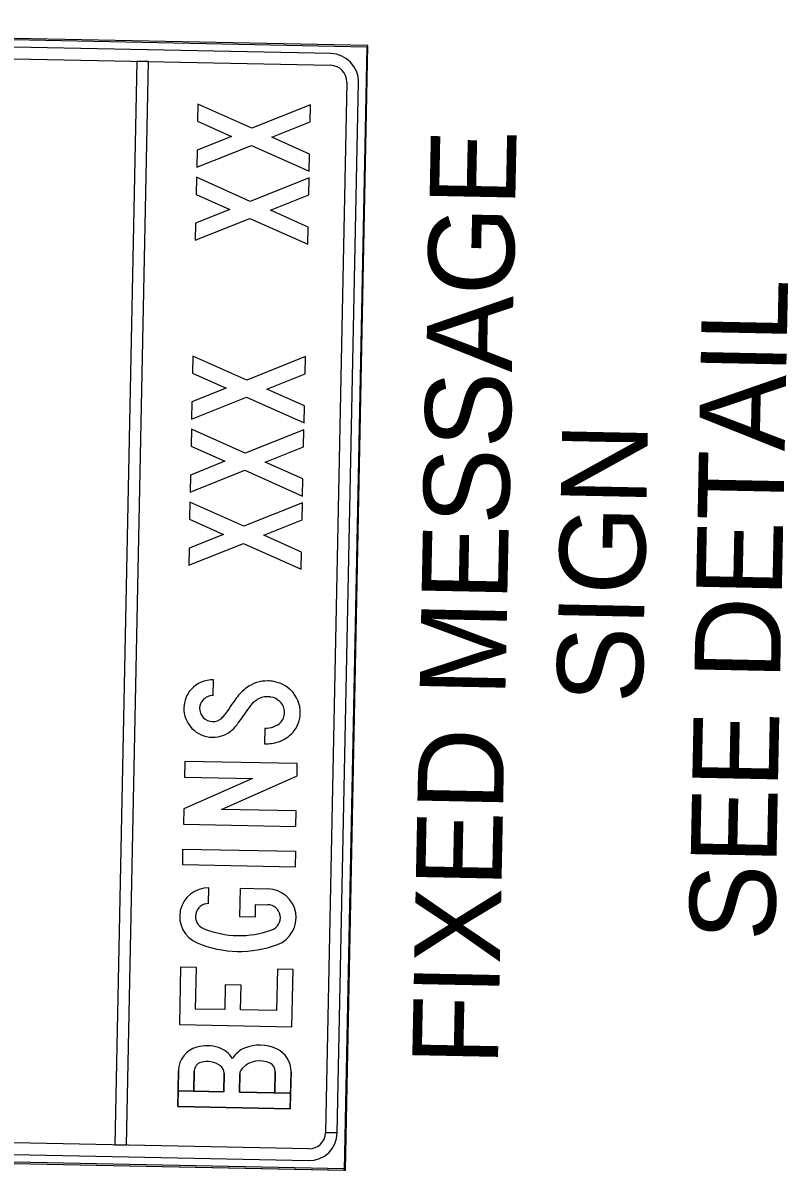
# Model space of a CAD drawing. Extents: x 331323 to 388339, y 121519 to 205315.
# Drawn here: x 366277 to 366812, y 140157 to 140960 of the extents above; entities that cross this region are included whole.
import ezdxf

# ---------------------------------------------------------------- set-up
doc = ezdxf.new("R2010")
doc.units = 0
doc.layers.add('CA-TEXT', color=7, linetype='Continuous')
doc.layers.add('P_MISC_TXT', color=7, linetype='Continuous')

msp = doc.modelspace()

# ---------------------------------------------------------------- linework, layer by layer
at = {"layer": 'CA-TEXT'}
for p, q in [((366518.36, 140944.39), (365730.94, 140960.23)), ((365731.75, 140959.39), (366517.53, 140943.58)), ((366492.41, 140938.75), (365756.65, 140953.56)), ((365756.49, 140945.36), (366492.24, 140930.55)), ((366517.53, 140943.58), (366501.7, 140156.98)), ((366502.52, 140156.97), (366518.36, 140944.39)), ((366503.49, 140918.84), (366488.69, 140183.17)), ((366496.89, 140183), (366511.69, 140918.68)), ((366406.84, 140343.58), (366407.06, 140354.6)), ((366406.84, 140343.58), (366407.06, 140354.6)), ((366406.84, 140343.58), (366407.06, 140354.6)), ((366439.71, 140342.92), (366448.17, 140342.75)), ((366439.71, 140342.92), (366448.17, 140342.75)), ((366439.71, 140342.92), (366448.17, 140342.75)), ((366476.97, 140171.84), (365741.22, 140186.64)), ((365741.05, 140178.44), (366476.81, 140163.64)), ((366488.69, 140183.17), (366496.89, 140183)), ((366496.89, 140182.92), (366488.69, 140183.09)), ((365715.1, 140172.81), (366501.69, 140156.98)), ((366501.71, 140157.8), (365715.93, 140173.61)), ((366501.69, 140156.98), (366501.71, 140157.8)), ((366501.7, 140156.98), (366502.52, 140156.97))]:
    msp.add_line(p, q, dxfattribs=at)
for points in [[(366451.07, 140880.21), (366477.91, 140890.93), (366478.15, 140902.9), (366437.04, 140886.48), (366399.4, 140903.31), (366399.16, 140891.34), (366422.78, 140880.78), (366398.75, 140871.19), (366398.51, 140859.22), (366436.8, 140874.51), (366477.21, 140856.45), (366477.45, 140868.42)], [(366451.07, 140880.21), (366477.91, 140890.93), (366478.15, 140902.9), (366437.04, 140886.48), (366399.4, 140903.31), (366399.16, 140891.34), (366422.78, 140880.78), (366398.75, 140871.19), (366398.51, 140859.22), (366436.8, 140874.51), (366477.21, 140856.45), (366477.45, 140868.42)], [(366451.07, 140880.21), (366477.91, 140890.93), (366478.15, 140902.9), (366437.04, 140886.48), (366399.4, 140903.31), (366399.16, 140891.34), (366422.78, 140880.78), (366398.75, 140871.19), (366398.51, 140859.22), (366436.8, 140874.51), (366477.21, 140856.45), (366477.45, 140868.42)], [(366450.04, 140829.04), (366476.88, 140839.76), (366477.12, 140851.73), (366436.01, 140835.31), (366398.37, 140852.13), (366398.13, 140840.17), (366421.75, 140829.61), (366397.72, 140820.01), (366397.48, 140808.05), (366435.77, 140823.34), (366476.18, 140805.28), (366476.42, 140817.25)], [(366450.04, 140829.04), (366476.88, 140839.76), (366477.12, 140851.73), (366436.01, 140835.31), (366398.37, 140852.13), (366398.13, 140840.17), (366421.75, 140829.61), (366397.72, 140820.01), (366397.48, 140808.05), (366435.77, 140823.34), (366476.18, 140805.28), (366476.42, 140817.25)], [(366450.04, 140829.04), (366476.88, 140839.76), (366477.12, 140851.73), (366436.01, 140835.31), (366398.37, 140852.13), (366398.13, 140840.17), (366421.75, 140829.61), (366397.72, 140820.01), (366397.48, 140808.05), (366435.77, 140823.34), (366476.18, 140805.28), (366476.42, 140817.25)], [(366447.52, 140703.87), (366474.36, 140714.59), (366474.6, 140726.56), (366433.49, 140710.14), (366395.85, 140726.96), (366395.61, 140714.99), (366419.23, 140704.44), (366395.2, 140694.84), (366394.96, 140682.87), (366433.25, 140698.17), (366473.67, 140680.11), (366473.91, 140692.07)], [(366447.52, 140703.87), (366474.36, 140714.59), (366474.6, 140726.56), (366433.49, 140710.14), (366395.85, 140726.96), (366395.61, 140714.99), (366419.23, 140704.44), (366395.2, 140694.84), (366394.96, 140682.87), (366433.25, 140698.17), (366473.67, 140680.11), (366473.91, 140692.07)], [(366447.52, 140703.87), (366474.36, 140714.59), (366474.6, 140726.56), (366433.49, 140710.14), (366395.85, 140726.96), (366395.61, 140714.99), (366419.23, 140704.44), (366395.2, 140694.84), (366394.96, 140682.87), (366433.25, 140698.17), (366473.67, 140680.11), (366473.91, 140692.07)], [(366446.49, 140652.7), (366473.33, 140663.42), (366473.57, 140675.38), (366432.46, 140658.96), (366394.82, 140675.79), (366394.58, 140663.82), (366418.2, 140653.26), (366394.17, 140643.67), (366393.93, 140631.7), (366432.22, 140647), (366472.64, 140628.94), (366472.88, 140640.9)], [(366446.49, 140652.7), (366473.33, 140663.42), (366473.57, 140675.38), (366432.46, 140658.96), (366394.82, 140675.79), (366394.58, 140663.82), (366418.2, 140653.26), (366394.17, 140643.67), (366393.93, 140631.7), (366432.22, 140647), (366472.64, 140628.94), (366472.88, 140640.9)], [(366446.49, 140652.7), (366473.33, 140663.42), (366473.57, 140675.38), (366432.46, 140658.96), (366394.82, 140675.79), (366394.58, 140663.82), (366418.2, 140653.26), (366394.17, 140643.67), (366393.93, 140631.7), (366432.22, 140647), (366472.64, 140628.94), (366472.88, 140640.9)], [(366445.46, 140601.52), (366472.3, 140612.24), (366472.54, 140624.21), (366431.43, 140607.79), (366393.79, 140624.62), (366393.55, 140612.65), (366417.17, 140602.09), (366393.14, 140592.5), (366392.9, 140580.53), (366431.19, 140595.82), (366471.61, 140577.76), (366471.85, 140589.73)], [(366445.46, 140601.52), (366472.3, 140612.24), (366472.54, 140624.21), (366431.43, 140607.79), (366393.79, 140624.62), (366393.55, 140612.65), (366417.17, 140602.09), (366393.14, 140592.5), (366392.9, 140580.53), (366431.19, 140595.82), (366471.61, 140577.76), (366471.85, 140589.73)], [(366445.46, 140601.52), (366472.3, 140612.24), (366472.54, 140624.21), (366431.43, 140607.79), (366393.79, 140624.62), (366393.55, 140612.65), (366417.17, 140602.09), (366393.14, 140592.5), (366392.9, 140580.53), (366431.19, 140595.82), (366471.61, 140577.76), (366471.85, 140589.73)], [(366468.69, 140432.91), (366468.87, 140441.57), (366390.14, 140443.15), (366389.92, 140432.13), (366437.49, 140431.17), (366389.47, 140409.95), (366389.25, 140399.07), (366467.98, 140397.48), (366468.2, 140408.5), (366415.85, 140409.56)], [(366468.69, 140432.91), (366468.87, 140441.57), (366390.14, 140443.15), (366389.92, 140432.13), (366437.49, 140431.17), (366389.47, 140409.95), (366389.25, 140399.07), (366467.98, 140397.48), (366468.2, 140408.5), (366415.85, 140409.56)], [(366468.69, 140432.91), (366468.87, 140441.57), (366390.14, 140443.15), (366389.92, 140432.13), (366437.49, 140431.17), (366389.47, 140409.95), (366389.25, 140399.07), (366467.98, 140397.48), (366468.2, 140408.5), (366415.85, 140409.56)], [(366388.68, 140370.72), (366388.9, 140381.75), (366467.63, 140380.16), (366467.41, 140369.14)], [(366388.68, 140370.72), (366388.9, 140381.75), (366467.63, 140380.16), (366467.41, 140369.14)], [(366388.68, 140370.72), (366388.9, 140381.75), (366467.63, 140380.16), (366467.41, 140369.14)], [(366454.36, 140268.59), (366429.17, 140269.1), (366429.51, 140286.35), (366418.49, 140286.57), (366418.14, 140269.32), (366397.68, 140269.73), (366398.26, 140298.86), (366387.24, 140299.08), (366386.43, 140258.93), (366465.16, 140257.35), (366465.97, 140297.5), (366454.94, 140297.72)], [(366454.36, 140268.59), (366429.17, 140269.1), (366429.51, 140286.35), (366418.49, 140286.57), (366418.14, 140269.32), (366397.68, 140269.73), (366398.26, 140298.86), (366387.24, 140299.08), (366386.43, 140258.93), (366465.16, 140257.35), (366465.97, 140297.5), (366454.94, 140297.72)], [(366454.36, 140268.59), (366429.17, 140269.1), (366429.51, 140286.35), (366418.49, 140286.57), (366418.14, 140269.32), (366397.68, 140269.73), (366398.26, 140298.86), (366387.24, 140299.08), (366386.43, 140258.93), (366465.16, 140257.35), (366465.97, 140297.5), (366454.94, 140297.72)]]:
    msp.add_lwpolyline(points, close=True, dxfattribs=at)
for points in [[(366410.03, 140489.22), (366410.25, 140500.24)], [(366410.03, 140489.22), (366410.25, 140500.24)], [(366410.03, 140489.22), (366410.25, 140500.24)], [(366446.19, 140466.44), (366445.97, 140455.42)], [(366446.19, 140466.44), (366445.97, 140455.42)], [(366446.19, 140466.44), (366445.97, 140455.42)], [(366448.39, 140353.77), (366428.91, 140354.16), (366428.51, 140334.48), (366439.53, 140334.26), (366439.71, 140342.92)], [(366448.39, 140353.77), (366428.91, 140354.16), (366428.51, 140334.48), (366439.53, 140334.26), (366439.71, 140342.92)], [(366448.39, 140353.77), (366428.91, 140354.16), (366428.51, 140334.48), (366439.53, 140334.26), (366439.71, 140342.92)], [(366385.78, 140226.66), (366385.28, 140201.46), (366464, 140199.88), (366464.52, 140225.76)], [(366396.8, 140226.43), (366396.52, 140212.27), (366385.5, 140212.49), (366385.78, 140226.66)], [(366396.8, 140226.43), (366396.52, 140212.27), (366385.5, 140212.49), (366385.78, 140226.66)], [(366417.64, 140224.72), (366417.38, 140211.84), (366396.52, 140212.26), (366396.8, 140226.43)], [(366453.5, 140225.98), (366453.2, 140211.12), (366428.4, 140211.62), (366428.65, 140224.06)], [(366464.52, 140225.76), (366464.22, 140210.9), (366453.2, 140211.13), (366453.5, 140225.98)], [(366464.52, 140225.76), (366464.22, 140210.9), (366453.2, 140211.13), (366453.5, 140225.98)], [(366428.65, 140224.06), (366428.4, 140211.62), (366464.22, 140210.9), (366464, 140199.88), (366385.28, 140201.46), (366385.5, 140212.48), (366417.38, 140211.84), (366417.64, 140224.72)], [(366428.65, 140224.06), (366428.4, 140211.62), (366464.22, 140210.9), (366464, 140199.88), (366385.28, 140201.46), (366385.5, 140212.48), (366417.38, 140211.84), (366417.64, 140224.72)]]:
    msp.add_lwpolyline(points, dxfattribs=at)
for centre, radius, start, end in [((366492.01, 140919.07), 19.69, 358.84724, 88.84724), ((366492.01, 140919.07), 11.48, 358.84724, 88.84724), ((366477.21, 140183.32), 19.69, 268.84724, 358.84724), ((366477.21, 140183.32), 11.48, 268.84724, 358.84724)]:
    msp.add_arc(centre, radius, start, end, dxfattribs=at)
for centre, major_axis, start_param, end_param in [((366409.84, 140479.66), (-20.58, 0.41), 4.712389, 5.561989), ((366409.84, 140479.66), (-20.58, 0.41), 4.712389, 5.561989), ((366409.84, 140479.66), (-20.58, 0.41), 4.712389, 5.561989), ((366447.76, 140475.49), (-23.98, 0.48), 4.712389, 5.373599), ((366447.76, 140475.49), (-23.98, 0.48), 4.712389, 5.373599), ((366447.76, 140475.49), (-23.98, 0.48), 4.712389, 5.373599), ((366447.71, 140473.26), (-26.22, 0.53), 4.552917, 4.712389), ((366447.71, 140473.26), (-26.22, 0.53), 4.552917, 4.712389), ((366447.71, 140473.26), (-26.22, 0.53), 4.552917, 4.712389), ((366448.22, 140476.05), (-23.38, 0.47), 3.967076, 4.552917), ((366448.22, 140476.05), (-23.38, 0.47), 3.967076, 4.552917), ((366448.22, 140476.05), (-23.38, 0.47), 3.967076, 4.552917), ((366409.11, 140480.33), (-19.59, 0.39), 5.561989, 6.283185), ((366409.11, 140480.33), (-19.59, 0.39), 5.561989, 6.283185), ((366409.11, 140480.33), (-19.59, 0.39), 5.561989, 6.283185), ((366453.69, 140467.54), (-33.9, 0.68), 5.373599, 5.679143), ((366453.69, 140467.54), (-33.9, 0.68), 5.373599, 5.679143), ((366453.69, 140467.54), (-33.9, 0.68), 5.373599, 5.679143), ((366449.66, 140477.55), (-21.3, 0.43), 3.141593, 3.967076), ((366449.66, 140477.55), (-21.3, 0.43), 3.141593, 3.967076), ((366449.66, 140477.55), (-21.3, 0.43), 3.141593, 3.967076), ((366409.11, 140480.33), (-8.57, 0.17), 5.561989, 6.283185), ((366409.11, 140480.33), (-8.57, 0.17), 5.561989, 6.283185), ((366409.11, 140480.33), (-8.57, 0.17), 5.561989, 6.283185), ((366409.84, 140479.66), (-9.56, 0.19), 4.712389, 5.561989), ((366409.84, 140479.66), (-9.56, 0.19), 4.712389, 5.561989), ((366409.84, 140479.66), (-9.56, 0.19), 4.712389, 5.561989), ((366802.24, 140216.52), (-463.35, 9.32), 5.679143, 5.709053), ((366802.24, 140216.52), (-463.35, 9.32), 5.679143, 5.709053), ((366802.24, 140216.52), (-463.35, 9.32), 5.679143, 5.709053), ((366453.69, 140467.54), (-22.88, 0.46), 5.373599, 5.679143), ((366453.69, 140467.54), (-22.88, 0.46), 5.373599, 5.679143), ((366453.69, 140467.54), (-22.88, 0.46), 5.373599, 5.679143), ((366447.76, 140475.49), (-12.96, 0.26), 4.712389, 5.373599), ((366447.76, 140475.49), (-12.96, 0.26), 4.712389, 5.373599), ((366447.76, 140475.49), (-12.96, 0.26), 4.712389, 5.373599), ((366447.71, 140473.26), (-15.19, 0.31), 4.552917, 4.712389), ((366447.71, 140473.26), (-15.19, 0.31), 4.552917, 4.712389), ((366447.71, 140473.26), (-15.19, 0.31), 4.552917, 4.712389), ((366448.22, 140476.05), (-12.36, 0.25), 3.967076, 4.552917), ((366448.22, 140476.05), (-12.36, 0.25), 3.967076, 4.552917), ((366448.22, 140476.05), (-12.36, 0.25), 3.967076, 4.552917), ((366449.66, 140477.55), (-10.28, 0.21), 3.141593, 3.967076), ((366449.66, 140477.55), (-10.28, 0.21), 3.141593, 3.967076), ((366449.66, 140477.55), (-10.28, 0.21), 3.141593, 3.967076), ((366409.8, 140480.31), (-20.28, 0.41), 6.283184, 7.853982), ((366409.8, 140480.31), (-20.28, 0.41), 6.283184, 7.853982), ((366409.8, 140480.31), (-20.28, 0.41), 6.283184, 7.853982), ((366409.8, 140480.31), (-9.26, 0.19), 6.283183, 7.853981), ((366409.8, 140480.31), (-9.26, 0.19), 6.283183, 7.853981), ((366409.8, 140480.31), (-9.26, 0.19), 6.283183, 7.853981), ((366406.74, 140483.76), (-13.88, 0.28), 2.321595, 2.56746), ((366406.74, 140483.76), (-13.88, 0.28), 2.321595, 2.56746), ((366406.74, 140483.76), (-13.88, 0.28), 2.321595, 2.56746), ((366802.24, 140216.52), (-452.33, 9.1), 5.679143, 5.709053), ((366802.24, 140216.52), (-452.33, 9.1), 5.679143, 5.709053), ((366802.24, 140216.52), (-452.33, 9.1), 5.679143, 5.709053), ((366447.93, 140477.59), (-12.01, 0.24), 2.811358, 3.141593), ((366447.93, 140477.59), (-12.01, 0.24), 2.811358, 3.141593), ((366447.93, 140477.59), (-12.01, 0.24), 2.811358, 3.141593), ((366447.93, 140477.59), (-23.03, 0.46), 2.811358, 3.141593), ((366447.93, 140477.59), (-23.03, 0.46), 2.811358, 3.141593), ((366447.93, 140477.59), (-23.03, 0.46), 2.811358, 3.141593), ((366409.8, 140480.35), (-9.3, 0.19), 1.570796, 2.321595), ((366409.8, 140480.35), (-9.3, 0.19), 1.570796, 2.321595), ((366409.8, 140480.35), (-9.3, 0.19), 1.570796, 2.321595), ((366406.74, 140483.76), (-24.9, 0.5), 2.321595, 2.56746), ((366406.74, 140483.76), (-24.9, 0.5), 2.321595, 2.56746), ((366406.74, 140483.76), (-24.9, 0.5), 2.321595, 2.56746), ((366446.55, 140484.45), (-18.01, 0.36), 1.570816, 1.909918), ((366446.55, 140484.45), (-18.01, 0.36), 1.570816, 1.909918), ((366446.55, 140484.45), (-18.01, 0.36), 1.570816, 1.909918), ((366448.21, 140479.44), (-12.74, 0.26), 1.909925, 2.431476), ((366448.21, 140479.44), (-12.74, 0.26), 1.909925, 2.431476), ((366448.21, 140479.44), (-12.74, 0.26), 1.909925, 2.431476), ((366451.9, 140476.14), (-7.79, 0.16), 2.431476, 2.811358), ((366451.9, 140476.14), (-7.79, 0.16), 2.431476, 2.811358), ((366451.9, 140476.14), (-7.79, 0.16), 2.431476, 2.811358), ((366451.9, 140476.14), (-18.81, 0.38), 2.431476, 2.811358), ((366451.9, 140476.14), (-18.81, 0.38), 2.431476, 2.811358), ((366451.9, 140476.14), (-18.81, 0.38), 2.431476, 2.811358), ((366409.8, 140480.35), (-20.32, 0.41), 1.570796, 2.321595), ((366409.8, 140480.35), (-20.32, 0.41), 1.570796, 2.321595), ((366409.8, 140480.35), (-20.32, 0.41), 1.570796, 2.321595), ((366448.21, 140479.44), (-23.76, 0.48), 1.909925, 2.431476), ((366448.21, 140479.44), (-23.76, 0.48), 1.909925, 2.431476), ((366448.21, 140479.44), (-23.76, 0.48), 1.909925, 2.431476), ((366446.55, 140484.45), (-29.04, 0.58), 1.570808, 1.909921), ((366446.55, 140484.45), (-29.04, 0.58), 1.570808, 1.909921), ((366446.55, 140484.45), (-29.04, 0.58), 1.570808, 1.909921), ((366406.66, 140334.53), (-20.08, 0.4), 4.712389, 7.477539), ((366406.66, 140334.53), (-20.08, 0.4), 4.712389, 7.477539), ((366406.66, 140334.53), (-20.08, 0.4), 4.712389, 7.477539), ((366447.99, 140333.7), (-20.08, 0.4), 1.947239, 4.712389), ((366447.99, 140333.7), (-20.08, 0.4), 1.947239, 4.712389), ((366447.99, 140333.7), (-20.08, 0.4), 1.947239, 4.712389), ((366406.66, 140334.53), (-9.05, 0.18), 4.712389, 7.477539), ((366406.66, 140334.53), (-9.05, 0.18), 4.712389, 7.477539), ((366406.66, 140334.53), (-9.05, 0.18), 4.712389, 7.477539), ((366447.99, 140333.7), (-9.05, 0.18), 1.947239, 4.712389), ((366447.99, 140333.7), (-9.05, 0.18), 1.947239, 4.712389), ((366447.99, 140333.7), (-9.05, 0.18), 1.947239, 4.712389), ((366428.38, 140386.39), (-65.27, 1.31), 1.194353, 1.947239), ((366428.38, 140386.39), (-65.27, 1.31), 1.194353, 1.947239), ((366428.38, 140386.39), (-65.27, 1.31), 1.194353, 1.947239), ((366428.38, 140386.39), (-76.29, 1.54), 1.194353, 1.947239), ((366428.38, 140386.39), (-76.29, 1.54), 1.194353, 1.947239), ((366428.38, 140386.39), (-76.29, 1.54), 1.194353, 1.947239), ((366403.1, 140226.31), (-17.32, 0.35), 4.996183, 6.283185), ((366403.1, 140226.31), (-17.32, 0.35), 4.996183, 6.283185), ((366403.1, 140226.31), (-17.32, 0.35), 4.996183, 6.283185), ((366405.67, 140216.8), (-27.16, 0.55), 4.428595, 4.996183), ((366405.67, 140216.8), (-27.16, 0.55), 4.428595, 4.996183), ((366405.67, 140216.8), (-27.16, 0.55), 4.428595, 4.996183), ((366408.61, 140226.2), (-17.32, 0.35), 3.692503, 4.428595), ((366408.61, 140226.2), (-17.32, 0.35), 3.692503, 4.428595), ((366408.61, 140226.2), (-17.32, 0.35), 3.692503, 4.428595), ((366438.54, 140226.28), (-17.32, 0.35), 5.116125, 5.778288), ((366438.54, 140226.28), (-17.32, 0.35), 5.116125, 5.778288), ((366438.54, 140226.28), (-17.32, 0.35), 5.116125, 5.778288), ((366442.67, 140216.06), (-28.34, 0.57), 4.308652, 5.116125), ((366442.67, 140216.06), (-28.34, 0.57), 4.308653, 5.116125), ((366442.67, 140216.06), (-28.34, 0.57), 4.308653, 5.116125), ((366447.2, 140226.11), (-17.32, 0.35), 3.141593, 4.308652), ((366447.2, 140226.11), (-17.32, 0.35), 3.141593, 4.308652), ((366447.2, 140226.11), (-17.32, 0.35), 3.141593, 4.308652), ((366442.67, 140216.06), (-17.32, 0.35), 4.308652, 5.507992), ((366442.67, 140216.06), (-17.32, 0.35), 4.308652, 5.507992), ((366442.67, 140216.06), (-17.32, 0.35), 4.308652, 5.507992), ((366403.1, 140226.31), (-6.3, 0.13), 4.996183, 6.283185), ((366403.1, 140226.31), (-6.3, 0.13), 4.996183, 6.283185), ((366403.1, 140226.31), (-6.3, 0.13), 4.996183, 6.283185), ((366405.67, 140216.8), (-16.14, 0.32), 4.118003, 4.996183), ((366405.67, 140216.8), (-16.14, 0.32), 4.118003, 4.996183), ((366405.67, 140216.8), (-16.14, 0.32), 4.118003, 4.996183), ((366411.34, 140224.85), (-6.3, 0.13), 3.141593, 4.118003), ((366411.34, 140224.85), (-6.3, 0.13), 3.141593, 4.118003), ((366411.34, 140224.85), (-6.3, 0.13), 3.141593, 4.118003), ((366434.95, 140223.93), (-6.3, 0.13), 5.507992, 6.283185), ((366434.95, 140223.93), (-6.3, 0.13), 5.507992, 6.283185), ((366434.95, 140223.93), (-6.3, 0.13), 5.507992, 6.283185), ((366447.2, 140226.11), (-6.3, 0.13), 3.141593, 4.308652), ((366447.2, 140226.11), (-6.3, 0.13), 3.141593, 4.308652), ((366447.2, 140226.11), (-6.3, 0.13), 3.141593, 4.308652)]:
    msp.add_ellipse(centre, major_axis=major_axis, ratio=0.999993, start_param=start_param, end_param=end_param, dxfattribs=at)
at = {"layer": 'P_MISC_TXT'}
for p, q in [((366518.36, 140944.39), (365730.94, 140960.23)), ((366502.52, 140156.97), (366518.36, 140944.39)), ((366356.51, 140933.29), (366341.25, 140174.57)), ((366356.51, 140933.29), (366341.25, 140174.57)), ((366356.51, 140933.29), (366341.25, 140174.57)), ((366349.45, 140174.4), (366364.71, 140933.12)), ((366349.45, 140174.4), (366364.71, 140933.12)), ((366349.45, 140174.4), (366364.71, 140933.12)), ((366364.71, 140933.12), (366356.51, 140933.29)), ((366364.71, 140933.12), (366356.51, 140933.29)), ((366364.71, 140933.12), (366356.51, 140933.29)), ((365715.1, 140172.81), (366502.52, 140156.97)), ((366341.25, 140174.57), (366349.45, 140174.4)), ((366341.25, 140174.57), (366349.45, 140174.4)), ((366341.25, 140174.57), (366349.45, 140174.4))]:
    msp.add_line(p, q, dxfattribs=at)

# ---------------------------------------------------------------- texts
at = {"layer": 'CA-TEXT'}
for s, p in [('FIXED MESSAGE', (366609.23, 140229.64)), ('SEE DETAIL', (366803.03, 140316.94)), ('SIGN', (366710.36, 140483.47))]:
    msp.add_text(s, height=60, rotation=88.84622, dxfattribs=at).set_placement(p)

doc.saveas('drawing.dxf')
